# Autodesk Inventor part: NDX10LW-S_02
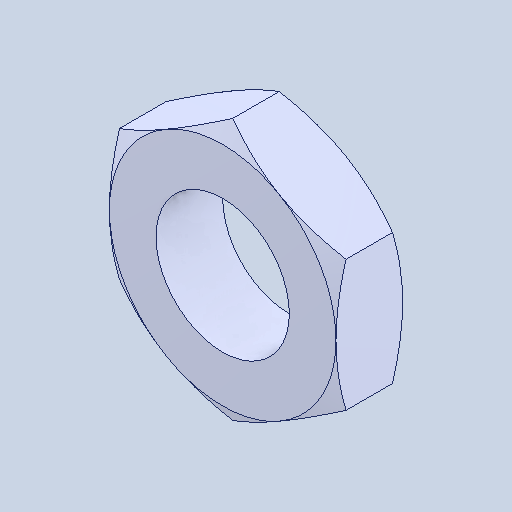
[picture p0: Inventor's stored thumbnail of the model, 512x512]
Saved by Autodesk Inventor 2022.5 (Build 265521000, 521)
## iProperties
Created: 2024-05
Part Number: NDX10LW-S_02
Material: 一般
Document SubType Name: Modeling
Designer: ImaoCorp
Density: 1 g/cm^3
Appearance: 既定
Author: ImaoCorp
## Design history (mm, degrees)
feature "NDX10LW-S_02"
node "ソリッド1"
